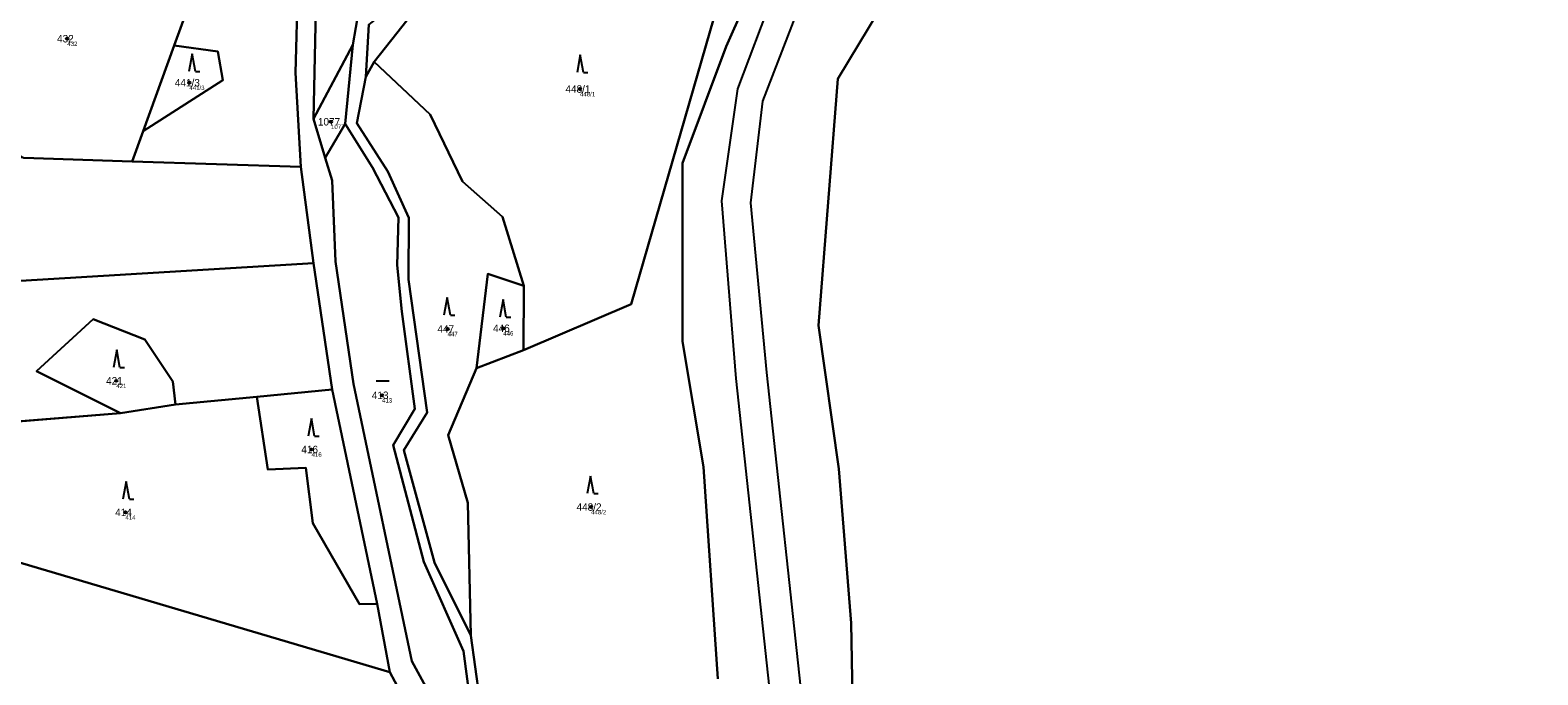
# Model space of a CAD drawing. Extents: x -554500 to -548272, y -1079733 to -1073730.
# Drawn here: x -551717.1 to -551374.3, y -1075871.5 to -1075724.9 of the extents above; entities that cross this region are included whole.
import ezdxf

# ---------------------------------------------------------------- set-up
doc = ezdxf.new("R2010")
doc.units = 0
for name, color, linetype in [('Definiční body', 7, 'Continuous'), ('Hranice parcel', 7, 'Continuous'), ('Parcelní čísla', 7, 'Continuous'), ('Polygon parcely', 7, 'Continuous'), ('Vnitřní kresba', 7, 'Continuous'), ('Značky kultur', 7, 'Continuous')]:
    doc.layers.add(name, color=color, linetype=linetype)

msp = doc.modelspace()

# ---------------------------------------------------------------- linework, layer by layer
at = {"layer": 'Definiční body'}
for centre in [(-551708.66, -1075726.86994), (-551680.91, -1075736.87994), (-551592.11, -1075738.31994), (-551648.71, -1075745.75994), (-551622.19, -1075792.85994), (-551609.54, -1075792.70994), (-551697.52, -1075804.66994), (-551637.1, -1075807.94994), (-551653.13, -1075820.26994), (-551695.45, -1075834.57994), (-551589.59, -1075833.36994)]:
    msp.add_circle(centre, 0.25, dxfattribs=at)
at = {"layer": 'Hranice parcel'}
for p, q in [((-551684.35, -1075728.45), (-551677.4, -1075709.23)), ((-551640.12, -1075723.66), (-551640.82, -1075735.56)), ((-551691.38, -1075747.87), (-551684.35, -1075728.45)), ((-551652.68, -1075745.12), (-551643.77, -1075728.23)), ((-551645.47, -1075746.26), (-551643.77, -1075728.23)), ((-551638.89, -1075732.14), (-551640.82, -1075735.56)), ((-551650.02, -1075753.97), (-551652.68, -1075745.12)), ((-551645.47, -1075746.26), (-551650.02, -1075753.97)), ((-551693.88, -1075754.77), (-551691.38, -1075747.87)), ((-551693.88, -1075754.77), (-551718.57, -1075753.94)), ((-551655.54, -1075755.99), (-551693.88, -1075754.77)), ((-551652.66, -1075777.89), (-551655.54, -1075755.99)), ((-551648.48, -1075806.64), (-551652.66, -1075777.89)), ((-551604.95, -1075797.71), (-551604.89, -1075783.04)), ((-551615.63, -1075801.77), (-551604.95, -1075797.71)), ((-551665.6, -1075808.28), (-551684.08, -1075810.05)), ((-551648.48, -1075806.64), (-551665.6, -1075808.28)), ((-551638.2, -1075855.38), (-551648.48, -1075806.64)), ((-551696.57, -1075812), (-551743.14, -1075815.78)), ((-551684.08, -1075810.05), (-551696.57, -1075812)), ((-551635.36, -1075870.93), (-551638.2, -1075855.38)), ((-551633.08, -1075875.15), (-551635.36, -1075870.93))]:
    msp.add_line(p, q, dxfattribs=at)
for points in [[(-551376.14, -1075528.04), (-551402.75, -1075579.49), (-551441.98, -1075622.04), (-551488.01, -1075668.18), (-551509.93, -1075696.87), (-551533.46, -1075736.03), (-551537.91, -1075792.05), (-551533.26, -1075824.67), (-551530.47, -1075859.76), (-551529.75, -1075897.45)], [(-551560.75, -1075872.41), (-551564.05, -1075824.19), (-551568.79, -1075795.75), (-551568.78, -1075755.17), (-551558.84, -1075728.67), (-551539.1, -1075684.12), (-551467.34, -1075599.01), (-551459.35, -1075584.9)], [(-551587.91, -1075625.77), (-551594.43, -1075630.08), (-551608.2, -1075637.39), (-551625.4, -1075652.79), (-551648.43, -1075682.33), (-551654.36, -1075696.39), (-551656.22, -1075714.82), (-551656.78, -1075734.63), (-551655.54, -1075755.99)], [(-551585.38, -1075629.65), (-551608.75, -1075643.98), (-551622.11, -1075656.61), (-551628.14, -1075663.2), (-551643.57, -1075684.48), (-551647.9, -1075692.99), (-551651.95, -1075709.72), (-551652.68, -1075745.12)], [(-551643.77, -1075728.23), (-551642.39, -1075720.35), (-551630.63, -1075693.57), (-551623.73, -1075689.94), (-551613.7, -1075675.62), (-551597.79, -1075662.9), (-551583.64, -1075648.93), (-551575.78, -1075644.44)], [(-551604.95, -1075797.71), (-551580.44, -1075787.2), (-551547.47, -1075673.1), (-551568, -1075682.57)], [(-551568, -1075682.57), (-551565.64, -1075684.58), (-551600.73, -1075702.56), (-551627.47, -1075717.6), (-551638.89, -1075732.14)], [(-551691.38, -1075747.87), (-551673.31, -1075736.33), (-551674.47, -1075729.79), (-551684.35, -1075728.45)], [(-551604.89, -1075783.04), (-551609.71, -1075767.41), (-551618.83, -1075759.36), (-551626.15, -1075744.11), (-551638.89, -1075732.14)], [(-551640.82, -1075735.56), (-551642.84, -1075746.05), (-551635.79, -1075757.1), (-551631, -1075767.64), (-551631.11, -1075781.66), (-551626.81, -1075811.83), (-551632.13, -1075820.45), (-551625.16, -1075846), (-551616.89, -1075862.57)], [(-551616.61, -1075893.57), (-551616.14, -1075891.18), (-551615.03, -1075893.07), (-551618.59, -1075866.13), (-551627.62, -1075845.83), (-551634.61, -1075819.32), (-551629.63, -1075811.04), (-551632.64, -1075788.89), (-551633.67, -1075778.33), (-551633.4, -1075767.49), (-551639.28, -1075756.16), (-551645.47, -1075746.26)], [(-551650.02, -1075753.97), (-551648.46, -1075759.15), (-551647.67, -1075777.51), (-551643.61, -1075805.38), (-551630.3, -1075868.41), (-551616.61, -1075893.57)], [(-551652.66, -1075777.89), (-551748.24, -1075783.67), (-551797.49, -1075786.43), (-551806.95, -1075785.78)], [(-551604.89, -1075783.04), (-551613.06, -1075780.33), (-551615.63, -1075801.77)], [(-551684.08, -1075810.05), (-551684.64, -1075804.8), (-551691.04, -1075795.24), (-551702.75, -1075790.68), (-551715.64, -1075802.45), (-551696.57, -1075812)], [(-551616.89, -1075862.57), (-551617.59, -1075832.39), (-551622.07, -1075817.01), (-551615.63, -1075801.77)], [(-551638.2, -1075855.38), (-551642.24, -1075855.46), (-551652.83, -1075837.03), (-551654.46, -1075824.44), (-551663.09, -1075824.82), (-551665.6, -1075808.28)], [(-551635.36, -1075870.93), (-551775.93, -1075829.27), (-551780.93, -1075819.56)], [(-551616.89, -1075862.57), (-551612.01, -1075898.18), (-551611.38, -1075899.25)]]:
    msp.add_lwpolyline(points, dxfattribs=at)
at = {"layer": 'Polygon parcely'}
for points in [[(-551529.75, -1075897.45), (-551530.47, -1075859.76), (-551533.26, -1075824.67), (-551537.91, -1075792.05), (-551533.46, -1075736.03), (-551509.93, -1075696.87), (-551488.01, -1075668.18), (-551441.98, -1075622.04), (-551402.75, -1075579.49), (-551376.14, -1075528.04), (-551396.16, -1075525.8), (-551404.54, -1075528.55), (-551406.9, -1075529.33), (-551413.37, -1075528.01), (-551428.8, -1075524.85), (-551442.88, -1075555.83), (-551459.35, -1075584.9), (-551467.34, -1075599.01), (-551539.1, -1075684.12), (-551558.84, -1075728.67), (-551568.78, -1075755.17), (-551568.79, -1075795.75), (-551564.05, -1075824.19), (-551560.75, -1075872.41)], [(-551372.54, -1075528.44), (-551376.14, -1075528.04), (-551402.75, -1075579.49), (-551441.98, -1075622.04), (-551488.01, -1075668.18), (-551509.93, -1075696.87), (-551533.46, -1075736.03), (-551537.91, -1075792.05), (-551533.26, -1075824.67), (-551530.47, -1075859.76), (-551529.75, -1075897.45)], [(-551547.47, -1075673.1), (-551580.44, -1075787.2), (-551604.95, -1075797.71), (-551615.63, -1075801.77), (-551622.07, -1075817.01), (-551617.59, -1075832.39), (-551616.89, -1075862.57), (-551612.01, -1075898.18)], [(-551560.75, -1075872.41), (-551564.05, -1075824.19), (-551568.79, -1075795.75), (-551568.78, -1075755.17), (-551558.84, -1075728.67), (-551539.1, -1075684.12)], [(-551616.61, -1075893.57), (-551630.3, -1075868.41), (-551643.61, -1075805.38), (-551647.67, -1075777.51), (-551648.46, -1075759.15), (-551650.02, -1075753.97), (-551652.68, -1075745.12), (-551651.95, -1075709.72)], [(-551656.22, -1075714.82), (-551656.78, -1075734.63), (-551655.54, -1075755.99), (-551652.66, -1075777.89), (-551648.48, -1075806.64), (-551638.2, -1075855.38), (-551635.36, -1075870.93), (-551633.08, -1075875.15)], [(-551642.39, -1075720.35), (-551643.77, -1075728.23), (-551645.47, -1075746.26), (-551639.28, -1075756.16), (-551633.4, -1075767.49), (-551633.67, -1075778.33), (-551632.64, -1075788.89), (-551629.63, -1075811.04)], [(-551612.01, -1075898.18), (-551616.89, -1075862.57), (-551625.16, -1075846), (-551632.13, -1075820.45), (-551626.81, -1075811.83), (-551631.11, -1075781.66), (-551631, -1075767.64), (-551635.79, -1075757.1), (-551642.84, -1075746.05), (-551640.82, -1075735.56), (-551640.12, -1075723.66)], [(-551629.63, -1075811.04), (-551634.61, -1075819.32), (-551627.62, -1075845.83), (-551618.59, -1075866.13), (-551615.03, -1075893.07), (-551616.14, -1075891.18), (-551616.61, -1075893.57), (-551617.88, -1075900), (-551618.21, -1075901.65), (-551617.31, -1075903.18), (-551615.53, -1075906.2), (-551629.54, -1075927.5), (-551620.99, -1075953.42), (-551610.2, -1075969.23), (-551618.01, -1075990.96), (-551622.55, -1075996.76), (-551625.45, -1076001.42), (-551626.04, -1076020.14), (-551621.21, -1076034.95)]]:
    msp.add_lwpolyline(points, dxfattribs=at)
for points in [[(-551671.23, -1075667.6), (-551664.02, -1075672.26), (-551677.4, -1075709.23), (-551684.35, -1075728.45), (-551674.47, -1075729.79), (-551673.31, -1075736.33), (-551691.38, -1075747.87), (-551693.88, -1075754.77), (-551655.54, -1075755.99), (-551656.78, -1075734.63), (-551656.22, -1075714.82), (-551654.36, -1075696.39), (-551648.43, -1075682.33), (-551625.4, -1075652.79), (-551608.2, -1075637.39), (-551594.43, -1075630.08), (-551587.91, -1075625.77), (-551602.58, -1075606.81), (-551634.94, -1075628.7)], [(-551628.14, -1075663.2), (-551643.57, -1075684.48), (-551647.9, -1075692.99), (-551651.95, -1075709.72), (-551652.68, -1075745.12), (-551643.77, -1075728.23), (-551642.39, -1075720.35), (-551630.63, -1075693.57), (-551623.73, -1075689.94), (-551613.7, -1075675.62), (-551597.79, -1075662.9), (-551583.64, -1075648.93), (-551575.78, -1075644.44), (-551577.6, -1075641.64), (-551585.38, -1075629.65), (-551608.75, -1075643.98), (-551622.11, -1075656.61)], [(-551600.73, -1075702.56), (-551627.47, -1075717.6), (-551638.89, -1075732.14), (-551626.15, -1075744.11), (-551618.83, -1075759.36), (-551609.71, -1075767.41), (-551604.89, -1075783.04), (-551604.95, -1075797.71), (-551580.44, -1075787.2), (-551547.47, -1075673.1), (-551568, -1075682.57), (-551565.64, -1075684.58)], [(-551640.82, -1075735.56), (-551638.89, -1075732.14), (-551627.47, -1075717.6), (-551600.73, -1075702.56), (-551565.64, -1075684.58), (-551568, -1075682.57), (-551626.96, -1075713.37), (-551640.12, -1075723.66)], [(-551684.35, -1075728.45), (-551677.4, -1075709.23), (-551680.63, -1075708.37), (-551738.87, -1075692.97), (-551750.92, -1075698.18), (-551751.24, -1075715.19), (-551742.85, -1075720.91), (-551723.37, -1075716.29), (-551723.06, -1075720.09), (-551733.64, -1075722.68), (-551747.7, -1075734.4), (-551743.91, -1075740.29), (-551718.57, -1075753.94), (-551693.88, -1075754.77), (-551691.38, -1075747.87)], [(-551691.38, -1075747.87), (-551673.31, -1075736.33), (-551674.47, -1075729.79), (-551684.35, -1075728.45)], [(-551643.77, -1075728.23), (-551652.68, -1075745.12), (-551650.02, -1075753.97), (-551645.47, -1075746.26)], [(-551609.71, -1075767.41), (-551618.83, -1075759.36), (-551626.15, -1075744.11), (-551638.89, -1075732.14), (-551640.82, -1075735.56), (-551642.84, -1075746.05), (-551635.79, -1075757.1), (-551631, -1075767.64), (-551631.11, -1075781.66), (-551626.81, -1075811.83), (-551632.13, -1075820.45), (-551625.16, -1075846), (-551616.89, -1075862.57), (-551617.59, -1075832.39), (-551622.07, -1075817.01), (-551615.63, -1075801.77), (-551613.06, -1075780.33), (-551604.89, -1075783.04)], [(-551798.47, -1075764.63), (-551806.95, -1075785.78), (-551797.49, -1075786.43), (-551748.24, -1075783.67), (-551652.66, -1075777.89), (-551655.54, -1075755.99), (-551693.88, -1075754.77), (-551718.57, -1075753.94), (-551751.77, -1075749.76), (-551768.98, -1075747), (-551782.69, -1075744.01)], [(-551615.03, -1075893.07), (-551618.59, -1075866.13), (-551627.62, -1075845.83), (-551634.61, -1075819.32), (-551629.63, -1075811.04), (-551632.64, -1075788.89), (-551633.67, -1075778.33), (-551633.4, -1075767.49), (-551639.28, -1075756.16), (-551645.47, -1075746.26), (-551650.02, -1075753.97), (-551648.46, -1075759.15), (-551647.67, -1075777.51), (-551643.61, -1075805.38), (-551630.3, -1075868.41), (-551616.61, -1075893.57), (-551616.14, -1075891.18)], [(-551652.66, -1075777.89), (-551748.24, -1075783.67), (-551797.49, -1075786.43), (-551806.95, -1075785.78), (-551800.69, -1075808.95), (-551785.08, -1075814.52), (-551764.46, -1075806.29), (-551748.77, -1075807.39), (-551743.14, -1075815.78), (-551696.57, -1075812), (-551715.64, -1075802.45), (-551702.75, -1075790.68), (-551691.04, -1075795.24), (-551684.64, -1075804.8), (-551684.08, -1075810.05), (-551665.6, -1075808.28), (-551648.48, -1075806.64)], [(-551615.63, -1075801.77), (-551604.95, -1075797.71), (-551604.89, -1075783.04), (-551613.06, -1075780.33)], [(-551715.64, -1075802.45), (-551696.57, -1075812), (-551684.08, -1075810.05), (-551684.64, -1075804.8), (-551691.04, -1075795.24), (-551702.75, -1075790.68)], [(-551652.83, -1075837.03), (-551654.46, -1075824.44), (-551663.09, -1075824.82), (-551665.6, -1075808.28), (-551684.08, -1075810.05), (-551696.57, -1075812), (-551743.14, -1075815.78), (-551780.93, -1075819.56), (-551775.93, -1075829.27), (-551635.36, -1075870.93), (-551638.2, -1075855.38), (-551642.24, -1075855.46)], [(-551648.48, -1075806.64), (-551665.6, -1075808.28), (-551663.09, -1075824.82), (-551654.46, -1075824.44), (-551652.83, -1075837.03), (-551642.24, -1075855.46), (-551638.2, -1075855.38)], [(-551635.36, -1075870.93), (-551775.93, -1075829.27), (-551780.93, -1075819.56), (-551806.11, -1075821.8), (-551812.24, -1075827.13), (-551802.02, -1075873.1), (-551797.07, -1075941.33), (-551787.36, -1075973.24), (-551777.19, -1075982.34), (-551719.58, -1076032.97), (-551686.83, -1076036.56), (-551637.36, -1076041.09), (-551632.56, -1076041.67), (-551641.95, -1075950.41), (-551640.54, -1075913.34), (-551641.32, -1075904.39), (-551641.65, -1075874.69), (-551633.08, -1075875.15)]]:
    msp.add_lwpolyline(points, close=True, dxfattribs=at)
at = {"layer": 'Vnitřní kresba'}
for p, q in [((-551547.66, -1075715.41), (-551556.3, -1075738.3)), ((-551541.44, -1075717.26), (-551550.61, -1075741.05)), ((-551556.3, -1075738.3), (-551559.94, -1075763.72)), ((-551550.61, -1075741.05), (-551553.31, -1075764.18)), ((-551559.94, -1075763.72), (-551556.68, -1075804.1)), ((-551553.31, -1075764.18), (-551549.67, -1075802.79)), ((-551556.68, -1075804.1), (-551534.77, -1076007.06)), ((-551549.67, -1075802.79), (-551527.63, -1076007.29))]:
    msp.add_line(p, q, dxfattribs=at)
at = {"layer": 'Značky kultur'}
for p, q in [((-551680.3, -1075730.3), (-551681.05, -1075734.3)), ((-551679.55, -1075734.3), (-551680.3, -1075730.3)), ((-551592.03, -1075730.54), (-551592.78, -1075734.54)), ((-551591.28, -1075734.54), (-551592.03, -1075730.54)), ((-551679.55, -1075734.3), (-551678.554, -1075734.3)), ((-551591.28, -1075734.54), (-551590.284, -1075734.54)), ((-551622.29, -1075785.73), (-551623.04, -1075789.73)), ((-551621.54, -1075789.73), (-551622.29, -1075785.73)), ((-551609.6, -1075786.2), (-551610.35, -1075790.2)), ((-551608.85, -1075790.2), (-551609.6, -1075786.2)), ((-551621.54, -1075789.73), (-551620.544, -1075789.73)), ((-551608.85, -1075790.2), (-551607.854, -1075790.2)), ((-551697.43, -1075797.63), (-551698.18, -1075801.63)), ((-551696.68, -1075801.63), (-551697.43, -1075797.63)), ((-551696.68, -1075801.63), (-551695.684, -1075801.63)), ((-551638.468, -1075804.67), (-551635.468, -1075804.67)), ((-551653.18, -1075813.22), (-551653.93, -1075817.22)), ((-551652.43, -1075817.22), (-551653.18, -1075813.22)), ((-551652.43, -1075817.22), (-551651.434, -1075817.22)), ((-551695.25, -1075827.54), (-551696, -1075831.54)), ((-551694.5, -1075831.54), (-551695.25, -1075827.54)), ((-551589.71, -1075826.32), (-551590.46, -1075830.32)), ((-551588.96, -1075830.32), (-551589.71, -1075826.32)), ((-551694.5, -1075831.54), (-551693.504, -1075831.54)), ((-551588.96, -1075830.32), (-551587.964, -1075830.32))]:
    msp.add_line(p, q, dxfattribs=at)

# ---------------------------------------------------------------- texts
at = {"layer": 'Definiční body'}
for s, p in [('432', (-551708.66, -1075728.526)), ('441/3', (-551680.91, -1075738.536)), ('448/1', (-551592.11, -1075739.976)), ('1077', (-551648.71, -1075747.416)), ('447', (-551622.19, -1075794.516)), ('446', (-551609.54, -1075794.366)), ('421', (-551697.52, -1075806.326)), ('413', (-551637.1, -1075809.606)), ('416', (-551653.13, -1075821.926)), ('414', (-551695.45, -1075836.236)), ('448/2', (-551589.59, -1075835.026))]:
    msp.add_text(s, height=0.999996, dxfattribs=at).set_placement(p)
at = {"layer": 'Parcelní čísla'}
for s, p in [('432', (-551710.985, -1075727.72)), ('441/3', (-551684.208, -1075737.73)), ('448/1', (-551595.408, -1075739.17)), ('1077', (-551651.684, -1075746.61)), ('446', (-551611.865, -1075793.56)), ('447', (-551624.515, -1075793.71)), ('421', (-551699.845, -1075805.52)), ('413', (-551639.425, -1075808.8)), ('416', (-551655.455, -1075821.12)), ('448/2', (-551592.888, -1075834.22)), ('414', (-551697.775, -1075835.43))]:
    msp.add_text(s, height=1.699998, dxfattribs=at).set_placement(p)

doc.saveas('drawing.dxf')
